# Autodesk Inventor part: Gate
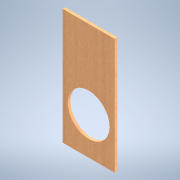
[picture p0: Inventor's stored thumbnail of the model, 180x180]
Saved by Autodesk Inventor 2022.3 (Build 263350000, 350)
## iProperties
Created: 2022-05
Part Number: Gate
Material: Wood (Cherry)
Document SubType Name: Modeling
Designer: elimb
Density: 0.63 g/cm^3
Appearance: Cherry - Natural Low Gloss
Author: elimb
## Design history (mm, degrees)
sketch "Sketch1"
  geometry: L1 (-60.96, -87.224)-(60.96, -87.224); L2 (60.96, -87.224)-(60.96, 184.607); L3 (60.96, 184.607)-(-60.96, 184.607); L4 (-60.96, 184.607)-(-60.96, -87.224); C1 r 49.124 at (0, 0); 2 further points
  constraints: 8 end point, 2 parallel, 1 centre point, 1 coincident, 1 horizontal, 1 midpoint, 1 perpendicular, 1 vertical alignment
  dimensions: "d0" = 98.2472 diameter of C1; "d1" = 121.92 distance of L1.start L1.end; "d2" = 87.2236 distance from line of L1 C1.centre; "d3" = 184.6072 distance from line of L3 C1.centre
extrude "Extrusion1" new body sketch "Sketch1" distance "d4" = 6.35; taper "d5" = 0 deg
body "Solid1"
